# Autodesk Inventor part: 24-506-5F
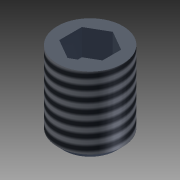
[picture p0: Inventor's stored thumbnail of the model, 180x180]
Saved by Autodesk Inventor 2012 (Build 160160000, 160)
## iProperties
Created: 2004-11
Part Number: 24-506-5F
Material: Steel, High Strength Low Alloy
Document SubType Name: Modeling
Designer: Autodesk, Inc.
Manufacturer: Standard
Standards Organization: Custom
Description: Set Screw, Flat Point, M5x6
Vendor: PARKER IPS
Catalog Web Link: http://www.parker.com/ead/cm1.asp?cmid=809
Mass: 0.787047 g
Surface Area: 1.49376 cm^2
Volume: 0.100389 cm^3
Density: 7.84 g/cm^3
CAGE: 1LJX3
Dept. ID: Product Design
Description #2: ---
Finish #1: ---
Finish #2: ---
Material ID: ---
Project Number: ---
Author: Autodesk, Inc.
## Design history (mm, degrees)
sketch "Sketch1"
  geometry: C1 r 2.5 at (0, 0)
  constraints: 1 centre point
  dimensions: "Dia" = 5 diameter of C1
extrude "Extrusion1" new body sketch "Sketch1" taper "d2" = 0 deg; distance "Length" = 6
chamfer "Chamfer1" distance "d3" = 0.5 (= 0.1 x Dia); stored, may be unused: second distance "d4" = 2, angle "d5" = 45 deg
thread "Thread1" dims "d6" = 10, "d7" = 0
sketch "Sketch2"
  geometry: L1 (0.866, 1.5)-(1.732, 0); L2 (1.732, 0)-(0.866, -1.5); L3 (0.866, -1.5)-(-0.866, -1.5); L4 (-0.866, -1.5)-(-1.732, 0); L5 (-1.732, 0)-(-0.866, 1.5); L6 (-0.866, 1.5)-(0.866, 1.5); 1 further point
  constraints: 12 end point, 1 horizontal, 12 other
  dimensions: "d8" = 3 distance between parallel lines of L3 L6 (computed from Dia)
extrude "Extrusion2" cut sketch "Sketch2" distance "d9" = 2; taper "d10" = 0 deg
body "Solid1"
